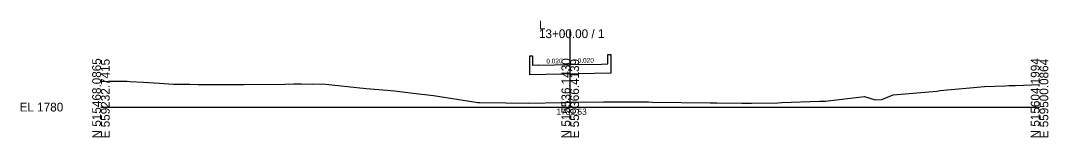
# Model space of a CAD drawing. Extents: x -26 to 1303, y -10 to 9545.
# Drawn here: x -25.7 to 302.8, y 7990.3 to 8027.6 of the extents above; entities that cross this region are included whole.
import ezdxf

# ---------------------------------------------------------------- set-up
doc = ezdxf.new("R2010")
doc.units = 0
for name, color, linetype in [('Exist Cross Section Cell', 7, 'Continuous'), ('Exist XS Center Line Elevation Label', 7, 'Continuous'), ('Exist XS Ground Line', 7, 'Continuous'), ('Prop XS Bridge', 7, 'Continuous'), ('Prop XS Dump Level', 7, 'Continuous'), ('Prop XS SE Text', 7, 'Continuous')]:
    doc.layers.add(name, color=color, linetype=linetype)

msp = doc.modelspace()

# ---------------------------------------------------------------- linework, layer by layer
at = {"layer": 'Exist Cross Section Cell'}
for p, q in [((150, 8000), (150, 8024.84)), ((0, 8000), (150, 8000)), ((150, 8000), (300, 8000))]:
    msp.add_line(p, q, dxfattribs=at)
at = {"layer": 'Exist XS Ground Line'}
for p, q in [((0, 8008.23), (2.39, 8008.28)), ((2.39, 8008.28), (4.04, 8008.28)), ((4.04, 8008.28), (8.41, 8008.25)), ((8.41, 8008.25), (9.19, 8008.18)), ((9.19, 8008.18), (13.57, 8008.01)), ((13.57, 8008.01), (18.71, 8007.68)), ((18.71, 8007.68), (23.2, 8007.33)), ((23.2, 8007.33), (28.36, 8007.29)), ((28.36, 8007.29), (31.12, 8007.23)), ((31.12, 8007.23), (33.53, 8007.24)), ((33.53, 8007.24), (45.62, 8007.18)), ((45.62, 8007.18), (58.79, 8007.33)), ((58.79, 8007.33), (61.6, 8007.43)), ((61.6, 8007.43), (64.06, 8007.41)), ((64.06, 8007.41), (67.68, 8007.3)), ((67.68, 8007.3), (70.84, 8007.47)), ((70.84, 8007.47), (84.82, 8005.89)), ((268.2, 8005.3), (282.44, 8006.53)), ((282.44, 8006.53), (289.01, 8006.84)), ((289.01, 8006.84), (290.13, 8006.85)), ((290.13, 8006.85), (290.77, 8006.86)), ((290.77, 8006.86), (291.46, 8006.87)), ((291.46, 8006.87), (292.31, 8006.9)), ((292.31, 8006.9), (300, 8007.2)), ((84.82, 8005.89), (91.44, 8005.41)), ((91.44, 8005.41), (93.84, 8005.18)), ((93.84, 8005.18), (99.81, 8004.4)), ((99.81, 8004.4), (106.26, 8003.74)), ((106.26, 8003.74), (119.85, 8001.54)), ((231.47, 8001.94), (244.02, 8003.35)), ((244.02, 8003.35), (247.47, 8002.36)), ((249.64, 8002.41), (253.17, 8003.92)), ((253.17, 8003.92), (267.2, 8005.07)), ((267.2, 8005.07), (268.2, 8005.3)), ((119.85, 8001.54), (120.48, 8001.51)), ((120.48, 8001.51), (121.03, 8001.51)), ((121.03, 8001.51), (129.44, 8001.33)), ((129.44, 8001.33), (136.63, 8001.24)), ((136.63, 8001.24), (147.37, 8001.49)), ((147.37, 8001.49), (148.13, 8001.52)), ((148.13, 8001.52), (148.74, 8001.5)), ((148.74, 8001.5), (150, 8001.53)), ((150, 8001.53), (154.37, 8001.64)), ((154.37, 8001.64), (154.91, 8001.6)), ((154.91, 8001.6), (160.63, 8001.7)), ((160.63, 8001.7), (161.29, 8001.69)), ((161.29, 8001.69), (174.96, 8001.65)), ((174.96, 8001.65), (176.29, 8001.61)), ((176.29, 8001.61), (194.7, 8001.35)), ((194.7, 8001.35), (196.8, 8001.31)), ((196.8, 8001.31), (204.87, 8001.28)), ((204.87, 8001.28), (207.4, 8001.27)), ((207.4, 8001.27), (207.88, 8001.29)), ((207.88, 8001.29), (216.34, 8001.41)), ((216.34, 8001.41), (217.65, 8001.45)), ((217.65, 8001.45), (229.67, 8001.87)), ((229.67, 8001.87), (230.22, 8001.87)), ((230.22, 8001.87), (231.47, 8001.94)), ((247.47, 8002.36), (249.64, 8002.41))]:
    msp.add_line(p, q, dxfattribs=at)
at = {"layer": 'Prop XS Bridge'}
for p, q in [((137, 8016.32), (137, 8013.32)), ((138, 8016.32), (137, 8016.32)), ((138, 8013.32), (138, 8016.32)), ((162, 8013.8), (162, 8016.8)), ((162, 8016.8), (163, 8016.8)), ((163, 8016.8), (163, 8013.8)), ((137, 8013.32), (137, 8010.32)), ((140, 8013.36), (138, 8013.32)), ((140, 8013.36), (150, 8013.56)), ((150, 8013.56), (160, 8013.76)), ((160, 8013.76), (162, 8013.8)), ((163, 8013.8), (163, 8010.8)), ((163, 8010.8), (137, 8010.32))]:
    msp.add_line(p, q, dxfattribs=at)
at = {"layer": 'Prop XS Dump Level'}
for p, q in [((140, 8013.36), (150, 8013.56)), ((150, 8013.56), (160, 8013.76))]:
    msp.add_line(p, q, dxfattribs=at)

# ---------------------------------------------------------------- texts
at = {"layer": 'Exist Cross Section Cell'}
for s, p in [('L', (140, 8024.84)), ('13+00.00 / 1', (140, 8022.04)), ('EL 1780', (-26, 7998.6))]:
    msp.add_text(s, height=2.8, dxfattribs=at).set_placement(p)
for s, p in [('N 515468.0865', (0, 7990)), ('E 559232.7415', (2.8, 7990)), ('N 515536.1430', (150, 7990)), ('E 559366.4139', (152.8, 7990)), ('N 515604.1994', (300, 7990)), ('E 559500.0864', (302.8, 7990))]:
    msp.add_text(s, height=2.8, rotation=90, dxfattribs=at).set_placement(p)
at = {"layer": 'Exist XS Center Line Elevation Label'}
msp.add_text('1781.53', height=2, dxfattribs=at).set_placement((145.59, 7997.53))
at = {"layer": 'Prop XS SE Text'}
for p in [(142.38, 8013.91), (152.38, 8014.11)]:
    msp.add_text('0.020', height=1.5, rotation=1.1458, dxfattribs=at).set_placement(p)

doc.saveas('drawing.dxf')
